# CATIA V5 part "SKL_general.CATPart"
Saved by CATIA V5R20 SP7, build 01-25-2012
Part number: SKL_general
Publications: "plan_ref", "origine", "Point.2", "Point.3"
Bounding box of the stored display mesh (mm): x 0 to 0, y 0 to 100, z 0 to 150
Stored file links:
  F:\IAO_placube\SKL_general.CATPart
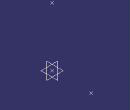
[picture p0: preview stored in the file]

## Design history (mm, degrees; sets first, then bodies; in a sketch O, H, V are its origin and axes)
Body1 (main body)
  Plane1 "plan_ref": type Offset, RefPlane yz-plane, Offset 0
  Point1 "origine": type OnPlane, Support Plane1, H 0, V 0, Direction (0, 1, 0)
  Point2: type OnPlane, Support Plane1, H 100, V 0, Direction (0, 1, 0)
  Point3: type OnPlane, Support Plane1, H 0, V 150, Direction (0, 1, 0)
